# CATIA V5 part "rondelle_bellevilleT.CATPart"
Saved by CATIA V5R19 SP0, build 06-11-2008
Part number: rondelle_bellevilleT
Publications: "Axe", "Appui_arbre", "Appui_alesage"
Material "Acier": density 7860 kg/m3, Young's modulus 2e+11 Pa, Poisson ratio 0.266, thermal expansion 1.17e-05 1/K
Bounding box of the stored display mesh (mm): x 0 to 1.6, y -24.997 to 24.997, z -24.865 to 24.865
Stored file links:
  U:\Rendu_cfao_elguidj\rondelle_bellevilleT.CATPart
  C:\Users\Martin\Documents\IFMA\Cfao\Projet S3\Bibliothèque Catia\rondelle_belleville.txt
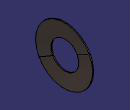
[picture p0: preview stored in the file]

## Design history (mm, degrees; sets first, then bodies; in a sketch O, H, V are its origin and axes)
Parameters
  `Diametre exterieur` = 25 mm {design table}
  `Diametre interieur` = 12.2 mm {design table}
  epaisseur_tole = 0.9 mm {design table}
  hauteur_vide = 1.6 mm {design table}
  course = 0 mm
  hauteur = 1.6 mm {= hauteur_vide -course}
  `Diametre nominal` = 12 mm {design table}
  course_maxi = 0.7 mm {design table}
  `Force_75%` = 870 (force) {design table}
Body1 (main body)
  Sketch1 on xy-plane, origin (0, 0, 0), H (1, 0, 0), V (0, 1, 0)
    point P1 (0.7014, 25)
    line L1 (0.7014, 25) -> (0, 12.2494)
    point P2 (0, 12.2494)
    line L2 (0, 12.2494) -> (0.8986, 12.2)
    point P3 (0.8986, 12.2)
    line L3 (0.8986, 12.2) -> (1.6, 24.9506)
    point P4 (1.6, 24.9506)
    line L4 (1.6, 24.9506) -> (0.7014, 25)
    axis line L5 (0, 0) -> (1.6, 0)
    length L5 = 1.6 {= Sketch1.distance(P2 P4 H)}
    distance P1 H = 25 {= `Diametre exterieur`}
    distance P3 H = 12.2 {= `Diametre interieur`}
    distance P2 P4 H = 1.6 {= hauteur}
    distance L3 L1 = 0.9 {= epaisseur_tole}
    coincidence: P2 V
    perpendicularity: L2 L1
    parallelism: L4 L2
    horizontal: L5 H
  Shaft1: profile Sketch1, axis Sketch1.L5, angle 360
Relations
  design table, configuration 18, drives `Diametre nominal`, `Diametre interieur`, `Diametre exterieur`, epaisseur_tole, hauteur_vide, course_maxi, `Force_75%`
